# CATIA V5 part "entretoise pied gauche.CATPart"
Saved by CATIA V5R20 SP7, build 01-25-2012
Part number: entretoise pied gauche
Bounding box of the stored display mesh (mm): x 19.898 to 37.465, y -79 to -65, z 29.747 to 41.427
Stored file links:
  F:\Travaux\Modélisations\CFAO_2011\CFAO_2011_MMS\CFAO_2011_MMS_DONE\CFAO_2011_MMS_jboiteux\Catia\entretoise pied gauche.CATPart
  U:\finthinkmotion\stepper.CATProduct
  F:\Travaux\Modélisations\CFAO_2011\CFAO_2011_MMS\CFAO_2011_MMS_DONE\CFAO_2011_MMS_jboiteux\Catia\Part1.CATPart
  F:\Travaux\Modélisations\CFAO_2011\CFAO_2011_MMS\CFAO_2011_MMS_DONE\CFAO_2011_MMS_jboiteux\Catia\Part2.CATPart
  F:\Travaux\Modélisations\CFAO_2011\CFAO_2011_MMS\CFAO_2011_MMS_DONE\CFAO_2011_MMS_jboiteux\Catia\compteur.CATPart
  F:\Travaux\Modélisations\CFAO_2011\CFAO_2011_MMS\CFAO_2011_MMS_DONE\CFAO_2011_MMS_jboiteux\Catia\bati.CATPart
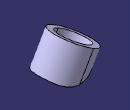
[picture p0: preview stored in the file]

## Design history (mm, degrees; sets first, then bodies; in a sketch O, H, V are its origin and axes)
Parameters
  rayontube = 9 mm {= External.royontubebati}
External parameters (linked from other documents)
  External.royontubebati = 9 mm
Set1
  Plane1: linked copy from another document
  Point1: linked copy from another document
  Plane2: linked copy from another document
  Plane3: linked copy from another document
  DatumCurve1: linked copy from another document
  Plane4: linked copy from another document
  DatumSurface1: linked copy from another document
Body1 (main body)
  Plane5: stored without definition
  Sketch1 on Plane1, origin (-14.4328, 0, 24.9983), H (0, 1, 0), V (0.866, 0, 0.5)
    circle A1 centre (-72, 41.4454) radius 5
    point P1 (-72, 41.4454)
    reference projected point E1 (-72, 41.4454) from Point1
    circle A2 centre (-72, 41.4454) radius 7
    point P2 (-72, 41.4454)
    reference projected point E2 (-72, 41.4454) from Point1
    radius A1 = 5 {= rayontube *5/9}
    radius A2 = 7 {= rayontube *5/9+2mm}
    coincidence: E1 P1, E2 P2
  Pad1: profile Sketch1, direction (0.5, 0, -0.866), up to Plane2, opposite side length -9 {= -rayontube}
  Sketch2 on Plane3, origin (42.31, 0, 0), H (0, 1, 0), V (0, 0, 1)
    projected circle E1 centre (-72, 20) radius 12 from edge of DatumCurve1
  Pocket1: profile Sketch2, direction (-1, 0, 0), up to Plane4, opposite side up to face of DatumSurface1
